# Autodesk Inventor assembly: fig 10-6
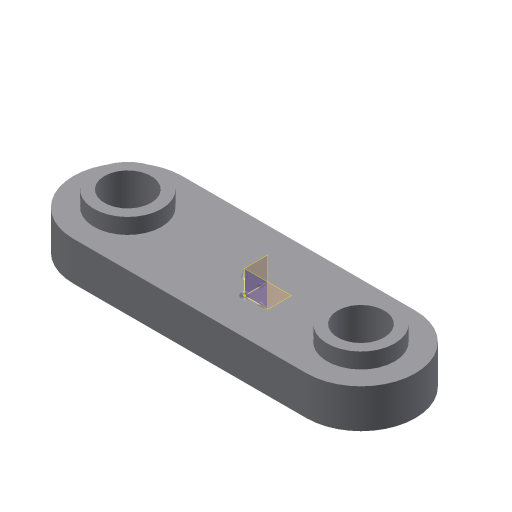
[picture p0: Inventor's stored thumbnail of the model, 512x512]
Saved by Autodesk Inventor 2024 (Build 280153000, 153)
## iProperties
Created: 2010-08
Part Number: fig 10-6
Document SubType Name: Assembly
Designer: CADSoft
Author: CADSoft
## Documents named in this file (2)
- D:\PROJECTS\Project 2023\RESOURCES INVENTOR 2024\RESOURCES INVENTOR 2024\Inventor_2023_Part\Inventor_2024_Part\c10_Inv_2024_prt\fig 10-6.iam
- D:\PROJECTS\Project 2023\RESOURCES INVENTOR 2024\RESOURCES INVENTOR 2024\Inventor_2023_Part\Inventor_2024_Part\c10_Inv_2024_prt\Part6.ipt
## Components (1 placed, 1 different names)
1. Part6:1
